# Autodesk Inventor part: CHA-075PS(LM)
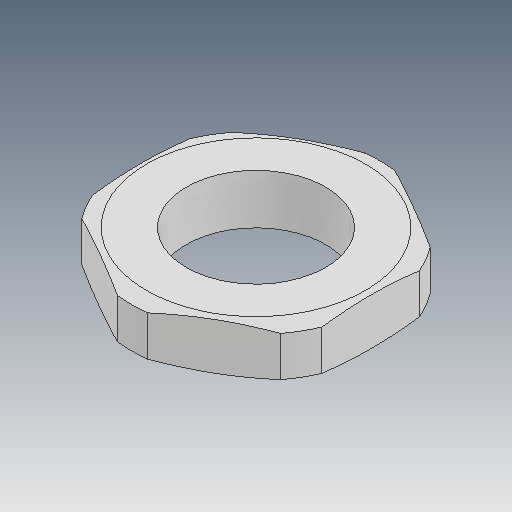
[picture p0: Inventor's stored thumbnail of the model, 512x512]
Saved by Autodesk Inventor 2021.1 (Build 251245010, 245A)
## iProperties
Created: 2021-05
Part Number: CHA-075PS(LM)
Material: Ogólny
Document SubType Name: Modeling
Designer: user
Density: 1 g/cm^3
Appearance: Domyślna
Author: user
Revision Number: ÈÎºÎ
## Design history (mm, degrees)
feature "M30x2.0 ÂÝÎÆ¿×1"
node "Bryła1"
